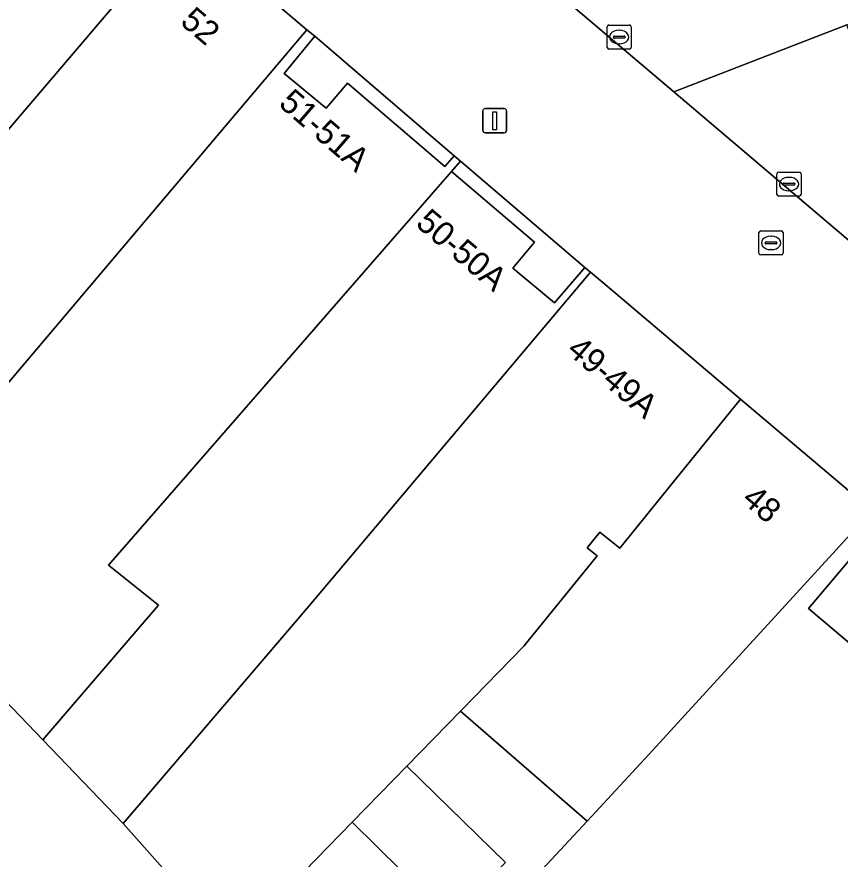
# Model space of a CAD drawing. Extents: x 160377 to 161131, y 383938 to 384853.
# Drawn here: x 160798.81 to 160832.91, y 384671.33 to 384706.21 of the extents above; entities that cross this region are included whole.
import ezdxf

# ---------------------------------------------------------------- set-up
doc = ezdxf.new("R2010")
doc.units = 0
for name, color, linetype in [('IMGEO_Erf', 7, 'Continuous'), ('IMGEO_Kolk', 7, 'Continuous'), ('IMGEO_Lichtmast', 7, 'Continuous'), ('IMGEO_Pand', 7, 'Continuous'), ('IMGEO_Pand_nummerreeks', 7, 'Continuous'), ('IMGEO_Pand_overbouw', 7, 'Continuous'), ('IMGEO_Rijbaan_lokaal_open', 7, 'Continuous'), ('IMGEO_Rioolput', 7, 'Continuous'), ('IMGEO_Verkeerseiland_open', 7, 'Continuous')]:
    doc.layers.add(name, color=color, linetype=linetype)

msp = doc.modelspace()

# ---------------------------------------------------------------- linework, layer by layer
at = {"layer": 'IMGEO_Erf'}
for points in [[(160816.925, 384700.463), (160811.145, 384705.406), (160809.878, 384703.859), (160811.619, 384702.434), (160812.503, 384703.469), (160816.537, 384700.011)], [(160822.33, 384695.835), (160817.183, 384700.242), (160816.812, 384699.809), (160820.241, 384696.882), (160819.348, 384695.804), (160821.08, 384694.368)], [(160838.154, 384682.402), (160834.692, 384685.368), (160831.597, 384681.712), (160835.078, 384678.766)]]:
    msp.add_lwpolyline(points, close=True, dxfattribs=at)
for points in [[(160816.757, 384668.855), (160812.695, 384672.862), (160807.704, 384667.744), (160803.216, 384672.805), (160799.885, 384676.274), (160791.714, 384684.785), (160790.622, 384685.922), (160787.653, 384683.073), (160781.488, 384689.495), (160784.457, 384692.345), (160783.188, 384693.666), (160779.632, 384697.243), (160777.29, 384695.235), (160773.424, 384691.921), (160773.054, 384691.604), (160773.14, 384691.511), (160789.658, 384673.773), (160793.805, 384669.319)], [(160808.825, 384658.296), (160822.422, 384672.91), (160817.184, 384677.466), (160814.953, 384675.179), (160819.039, 384671.195)]]:
    msp.add_lwpolyline(points, dxfattribs=at)
at = {"layer": 'IMGEO_Kolk'}
for p, q in [((160823.329, 384705.874), (160824.181, 384705.874)), ((160823.254, 384704.948), (160823.254, 384705.8)), ((160823.742, 384705.654), (160823.767, 384705.654)), ((160824.255, 384705.8), (160824.255, 384704.948)), ((160823.513, 384705.368), (160823.513, 384705.38)), ((160823.951, 384705.331), (160823.553, 384705.331)), ((160823.556, 384705.417), (160823.954, 384705.417)), ((160823.997, 384705.38), (160823.997, 384705.368)), ((160824.181, 384704.874), (160823.329, 384704.874)), ((160823.765, 384705.094), (160823.74, 384705.094)), ((160830.287, 384698.859), (160830.287, 384699.711)), ((160830.362, 384699.785), (160831.214, 384699.785)), ((160830.775, 384699.565), (160830.8, 384699.565)), ((160831.288, 384699.711), (160831.288, 384698.859)), ((160830.546, 384699.279), (160830.546, 384699.291)), ((160830.984, 384699.242), (160830.586, 384699.242)), ((160830.589, 384699.328), (160830.987, 384699.328)), ((160831.03, 384699.291), (160831.03, 384699.279)), ((160830.798, 384699.005), (160830.773, 384699.005)), ((160831.214, 384698.785), (160830.362, 384698.785))]:
    msp.add_line(p, q, dxfattribs=at)
for points in [[(160823.329, 384705.874), (160824.181, 384705.874)], [(160823.254, 384704.948), (160823.254, 384705.8)], [(160824.255, 384705.8), (160824.255, 384704.948)], [(160824.181, 384704.874), (160823.329, 384704.874)], [(160830.287, 384698.859), (160830.287, 384699.711)], [(160830.362, 384699.785), (160831.214, 384699.785)], [(160831.288, 384699.711), (160831.288, 384698.859)], [(160831.214, 384698.785), (160830.362, 384698.785)]]:
    msp.add_lwpolyline(points, dxfattribs=at)
for centre, radius, start, end in [((160823.331, 384705.798), 0.0765, 91.552, 178.448), ((160823.331, 384705.798), 0.0765, 91.552, 178.448), ((160824.179, 384705.798), 0.0765, 1.552, 88.448), ((160824.179, 384705.798), 0.0765, 1.552, 88.448), ((160823.553, 384705.377), 0.0403, 85.8775, 175.7526), ((160823.55, 384705.367), 0.0366, 178.938, 274.7102), ((160823.954, 384705.374), 0.043, 264.8664, 352.4533), ((160823.958, 384705.379), 0.0386, 1.7309, 96.639), ((160823.331, 384704.95), 0.0765, 181.552, 268.448), ((160823.331, 384704.95), 0.0765, 181.552, 268.448), ((160824.179, 384704.95), 0.0765, 271.552, 358.448), ((160824.179, 384704.95), 0.0765, 271.552, 358.448), ((160830.364, 384699.709), 0.0765, 91.552, 178.448), ((160830.364, 384699.709), 0.0765, 91.552, 178.448), ((160831.212, 384699.709), 0.0765, 1.552, 88.448), ((160831.212, 384699.709), 0.0765, 1.552, 88.448), ((160830.586, 384699.288), 0.0403, 85.8775, 175.7526), ((160830.583, 384699.278), 0.0366, 178.938, 274.7102), ((160830.987, 384699.285), 0.043, 264.8664, 352.4533), ((160830.991, 384699.29), 0.0386, 1.7309, 96.639), ((160830.364, 384698.861), 0.0765, 181.552, 268.448), ((160830.364, 384698.861), 0.0765, 181.552, 268.448), ((160831.212, 384698.861), 0.0765, 271.552, 358.448), ((160831.212, 384698.861), 0.0765, 271.552, 358.448)]:
    msp.add_arc(centre, radius, start, end, dxfattribs=at)
for centre, major_axis, ratio, start_param, end_param in [((160823.741, 384705.374), (-0.387, 0.002), 0.722429, 4.712389, 7.853982), ((160823.766, 384705.374), (-0.39, 0.002), 0.717154, 1.570796, 4.712389), ((160830.774, 384699.285), (-0.387, 0.002), 0.722429, 4.712389, 7.853982), ((160830.799, 384699.285), (-0.39, 0.002), 0.717154, 1.570796, 4.712389)]:
    msp.add_ellipse(centre, major_axis=major_axis, ratio=ratio, start_param=start_param, end_param=end_param, dxfattribs=at)
at = {"layer": 'IMGEO_Lichtmast'}
for p, q in [((160818.203, 384702.41), (160818.993, 384702.41)), ((160818.993, 384702.41), (160818.203, 384702.41)), ((160818.103, 384701.51), (160818.103, 384702.31)), ((160818.103, 384702.31), (160818.103, 384701.51)), ((160819.093, 384702.31), (160819.093, 384701.51)), ((160819.093, 384701.51), (160819.093, 384702.31)), ((160818.993, 384701.41), (160818.203, 384701.41)), ((160818.203, 384701.41), (160818.993, 384701.41))]:
    msp.add_line(p, q, dxfattribs=at)
msp.add_lwpolyline([(160818.523, 384702.285), (160818.673, 384702.285), (160818.673, 384701.535), (160818.523, 384701.535), (160818.523, 384702.285)], dxfattribs=at)
for centre, start, end in [((160818.203, 384702.31), 90, 180), ((160818.203, 384702.31), 90, 180), ((160818.993, 384702.31), 0, 90), ((160818.993, 384702.31), 360, 90), ((160818.203, 384701.51), 180, 270), ((160818.203, 384701.51), 180, 270), ((160818.993, 384701.51), 270, 0), ((160818.993, 384701.51), 270, 0)]:
    msp.add_arc(centre, 0.1, start, end, dxfattribs=at)
at = {"layer": 'IMGEO_Pand'}
for points in [[(160805.684, 384710.042), (160805.469, 384710.226), (160800.924, 384714.098), (160800.15, 384714.757), (160797.289, 384712.315), (160795.822, 384711.063), (160785.646, 384702.376), (160792.767, 384694.898)], [(160810.813, 384705.674), (160805.684, 384710.042), (160792.767, 384694.898), (160785.646, 384702.376), (160779.632, 384697.243), (160783.188, 384693.666), (160784.457, 384692.345), (160790.622, 384685.922), (160791.714, 384684.785), (160797.188, 384690.011), (160797.403, 384689.827)], [(160810.813, 384705.674), (160797.403, 384689.827), (160797.188, 384690.011), (160791.714, 384684.785), (160799.885, 384676.274), (160804.679, 384681.851), (160802.606, 384683.502), (160816.812, 384699.809), (160817.183, 384700.242), (160816.925, 384700.463), (160816.537, 384700.011), (160812.503, 384703.469), (160811.619, 384702.434), (160809.878, 384703.859), (160811.145, 384705.406)], [(160810.911, 384681.827), (160822.565, 384695.633), (160822.33, 384695.835), (160821.08, 384694.368), (160819.348, 384695.804), (160820.241, 384696.882), (160816.812, 384699.809), (160802.606, 384683.502), (160804.679, 384681.851), (160799.885, 384676.274), (160803.216, 384672.805)], [(160826.297, 384687.317), (160828.776, 384690.376), (160823.332, 384694.984), (160822.565, 384695.633), (160810.911, 384681.827), (160803.216, 384672.805), (160807.704, 384667.744), (160812.695, 384672.862), (160814.953, 384675.179), (160817.184, 384677.466), (160817.225, 384677.508), (160819.808, 384680.157), (160822.838, 384683.897), (160822.43, 384684.227), (160822.954, 384684.874), (160823.778, 384684.207)], [(160834.225, 384685.763), (160828.776, 384690.376), (160826.297, 384687.317), (160823.778, 384684.207), (160822.954, 384684.874), (160822.43, 384684.227), (160822.838, 384683.897), (160819.808, 384680.157), (160817.225, 384677.508), (160817.184, 384677.466), (160822.422, 384672.91), (160824.979, 384675.659)], [(160852.039, 384655.796), (160853.403, 384654.632), (160855.42, 384657.267), (160858.814, 384661.729), (160857.505, 384662.813), (160859.01, 384664.631), (160858.822, 384664.786), (160838.154, 384682.402), (160835.078, 384678.766), (160831.597, 384681.712), (160834.692, 384685.368), (160834.225, 384685.763), (160824.979, 384675.659), (160822.422, 384672.91), (160808.825, 384658.296), (160801.53, 384651.456), (160824.251, 384627.226), (160825.647, 384628.473), (160829.085, 384632.097), (160830.199, 384633.271), (160834.264, 384637.304)], [(160814.953, 384675.179), (160812.695, 384672.862), (160816.757, 384668.855), (160819.039, 384671.195)]]:
    msp.add_lwpolyline(points, close=True, dxfattribs=at)
at = {"layer": 'IMGEO_Pand_overbouw'}
for points in [[(160816.925, 384700.463), (160811.145, 384705.406), (160809.878, 384703.859), (160811.619, 384702.434), (160812.503, 384703.469), (160816.537, 384700.011)], [(160816.812, 384699.809), (160820.241, 384696.882), (160819.348, 384695.804), (160821.08, 384694.368), (160822.33, 384695.835), (160817.183, 384700.242)], [(160838.154, 384682.402), (160834.692, 384685.368), (160831.597, 384681.712), (160835.078, 384678.766)]]:
    msp.add_lwpolyline(points, close=True, dxfattribs=at)
at = {"layer": 'IMGEO_Rijbaan_lokaal_open'}
msp.add_lwpolyline([(160880.591, 384724.4), (160887.442, 384727.066), (160885.283, 384732.732), (160878.411, 384730.02), (160826.499, 384709.757), (160824.191, 384708.865), (160820.786, 384707.548), (160826.013, 384703.108), (160833.184, 384705.883)], close=True, dxfattribs=at)
for points in [[(160809.621, 384720.435), (160802.687, 384716.196), (160800.924, 384714.098), (160805.469, 384710.226), (160805.684, 384710.042), (160810.813, 384705.674), (160811.145, 384705.406), (160816.925, 384700.463), (160817.183, 384700.242), (160822.33, 384695.835), (160822.565, 384695.633), (160823.332, 384694.984), (160828.776, 384690.376), (160834.225, 384685.763)], [(160881.003, 384655.951), (160875.756, 384660.457), (160867.235, 384667.772), (160862.074, 384672.201), (160853.526, 384679.553), (160848.313, 384684.044), (160839.867, 384691.302), (160834.611, 384695.805), (160826.013, 384703.108), (160820.786, 384707.548), (160812.16, 384714.918)]]:
    msp.add_lwpolyline(points, dxfattribs=at)
at = {"layer": 'IMGEO_Rioolput'}
for p, q in [((160829.543, 384696.425), (160829.543, 384697.277)), ((160829.618, 384697.351), (160830.47, 384697.351)), ((160830.031, 384697.131), (160830.056, 384697.131)), ((160830.544, 384697.277), (160830.544, 384696.425)), ((160829.802, 384696.845), (160829.802, 384696.857)), ((160830.24, 384696.808), (160829.842, 384696.808)), ((160829.845, 384696.894), (160830.243, 384696.894)), ((160830.286, 384696.857), (160830.286, 384696.845)), ((160830.054, 384696.571), (160830.029, 384696.571)), ((160830.47, 384696.351), (160829.618, 384696.351))]:
    msp.add_line(p, q, dxfattribs=at)
for points in [[(160829.543, 384696.425), (160829.543, 384697.277)], [(160829.618, 384697.351), (160830.47, 384697.351)], [(160830.544, 384697.277), (160830.544, 384696.425)], [(160830.47, 384696.351), (160829.618, 384696.351)]]:
    msp.add_lwpolyline(points, dxfattribs=at)
for centre, radius, start, end in [((160829.62, 384697.275), 0.0765, 91.552, 178.448), ((160829.62, 384697.275), 0.0765, 91.552, 178.448), ((160830.468, 384697.275), 0.0765, 1.552, 88.448), ((160830.468, 384697.275), 0.0765, 1.552, 88.448), ((160829.842, 384696.854), 0.0403, 85.8775, 175.7526), ((160829.839, 384696.844), 0.0366, 178.938, 274.7102), ((160830.243, 384696.851), 0.043, 264.8664, 352.4533), ((160830.247, 384696.856), 0.0386, 1.7309, 96.639), ((160829.62, 384696.427), 0.0765, 181.552, 268.448), ((160829.62, 384696.427), 0.0765, 181.552, 268.448), ((160830.468, 384696.427), 0.0765, 271.552, 358.448), ((160830.468, 384696.427), 0.0765, 271.552, 358.448)]:
    msp.add_arc(centre, radius, start, end, dxfattribs=at)
for centre, major_axis, ratio, start_param, end_param in [((160830.03, 384696.851), (-0.387, 0.002), 0.722429, 4.712389, 7.853982), ((160830.055, 384696.851), (-0.39, 0.002), 0.717154, 1.570796, 4.712389)]:
    msp.add_ellipse(centre, major_axis=major_axis, ratio=ratio, start_param=start_param, end_param=end_param, dxfattribs=at)
at = {"layer": 'IMGEO_Verkeerseiland_open'}
msp.add_lwpolyline([(160826.013, 384703.108), (160834.611, 384695.805), (160838.999, 384697.485), (160837.049, 384702.497), (160834.8, 384701.574), (160833.184, 384705.883)], close=True, dxfattribs=at)

# ---------------------------------------------------------------- texts
at = {"layer": 'IMGEO_Pand_nummerreeks'}
for s, rotation, p in [('52', 319.5435, (160805.528, 384705.94)), ('51-51A', 319.1446, (160809.602, 384702.553)), ('50-50A', 319.6001, (160815.277, 384697.583)), ('49-49A', 319.595, (160821.53, 384692.322)), ('48', 319.595, (160828.782, 384686.149))]:
    msp.add_text(s, height=1, rotation=rotation, dxfattribs=at).set_placement(p)

doc.saveas('drawing.dxf')
